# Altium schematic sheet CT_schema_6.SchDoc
size 277 x 170 mm
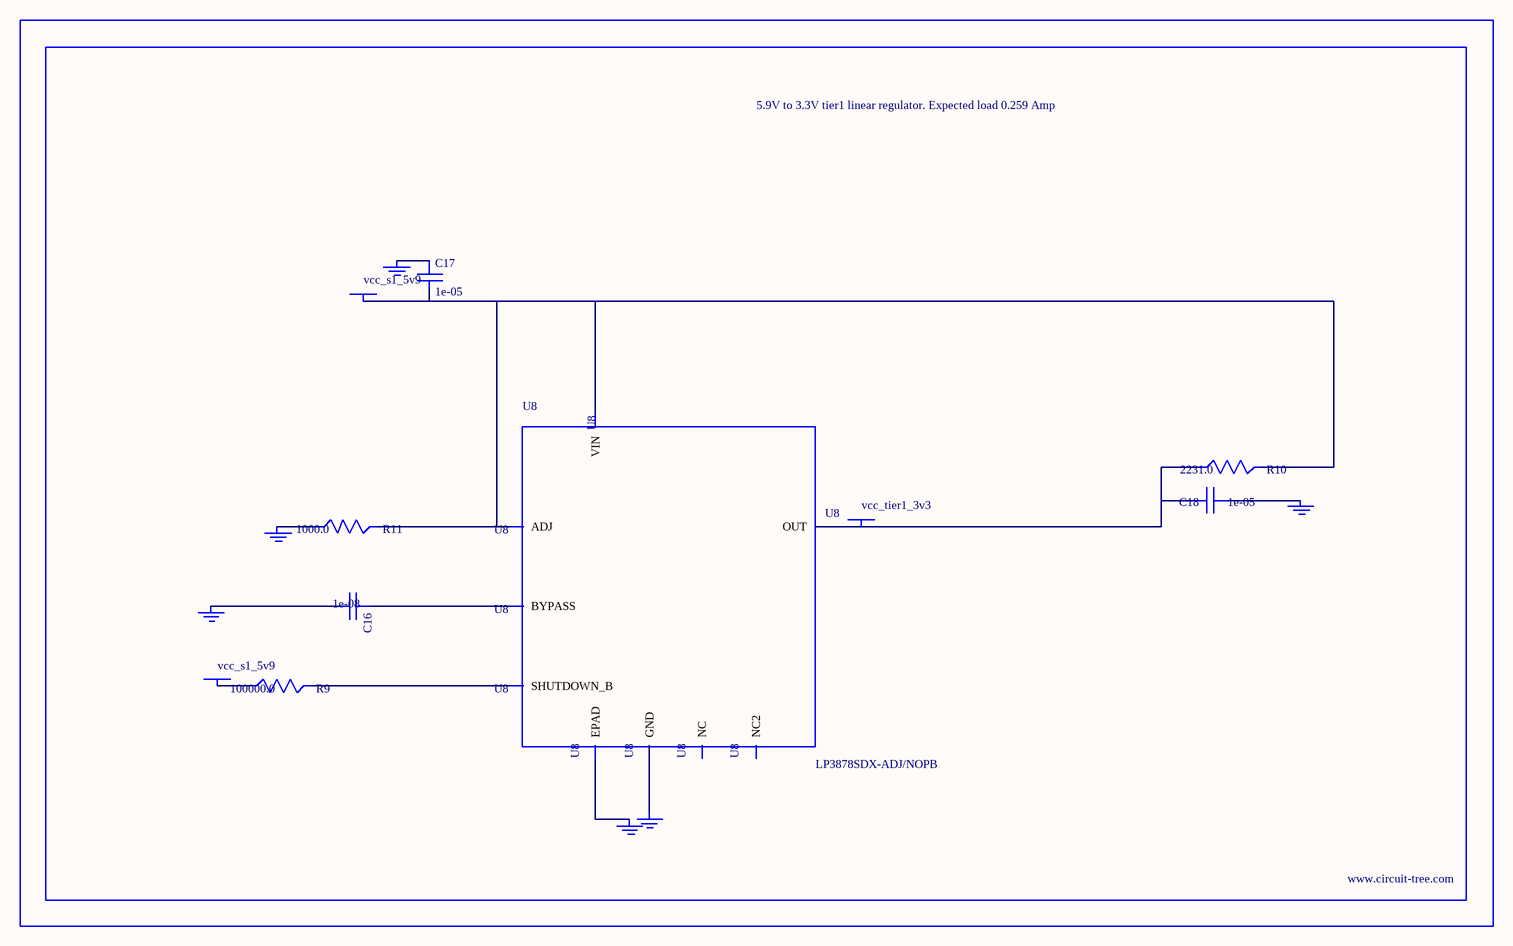
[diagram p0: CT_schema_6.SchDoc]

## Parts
BORDER5  (no value)
C16  1e-08  [C0402]
C17  1e-05  [C1206]
C18  1e-05  [C1210]
GND_INSTANCE_5_0  (no value)
GND_INSTANCE_5_1  (no value)
GND_INSTANCE_5_2  (no value)
GND_INSTANCE_5_3  (no value)
GND_INSTANCE_5_4  (no value)
GND_INSTANCE_5_5  (no value)
POWER_INSTANCE_5_0  vcc_s1_5v9
POWER_INSTANCE_5_1  vcc_s1_5v9
POWER_INSTANCE_5_2  vcc_tier1_3v3
R9  100000.0  [R0603]
R10  2231.0  [R0603]
R11  1000.0  [R0603]
U8  LP3878SDX-ADJ/NOPB  [WSON-8]

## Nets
NetC16_1: C16.1 U8.1(BYPASS)
NetC16_2: C16.2 GND_INSTANCE_5_0.0(GND)
NetC17_1: C17.1 GND_INSTANCE_5_1.0(GND)
NetC17_2: C17.2 POWER_INSTANCE_5_0.0(PWR) R10.2 R11.2 U8.4(VIN) U8.6(ADJ)
NetC18_1: C18.1 GND_INSTANCE_5_2.0(GND)
NetC18_2: C18.2 POWER_INSTANCE_5_2.0(PWR) R10.1 U8.5(OUT)
NetGND_INSTANCE_5_3_0: GND_INSTANCE_5_3.0(GND) R11.1
NetGND_INSTANCE_5_4_0: GND_INSTANCE_5_4.0(GND) U8.PAD(EPAD)
NetGND_INSTANCE_5_5_0: GND_INSTANCE_5_5.0(GND) U8.3(GND)
NetPOWER_INSTANCE_5_1_0: POWER_INSTANCE_5_1.0(PWR) R9.1
NetR9_2: R9.2 U8.8(SHUTDOWN_B)

Not connected (* = marked no-connect by the designer): U8 2(NC) 7(NC2)

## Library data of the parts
BORDER5 = BORDER_PAGE5
C16 = C0402C103K3RAC
C17 = C1206C106K3RACTU
C18 = GRM32DR61E106MA12L
GND_INSTANCE_5_0-GND_INSTANCE_5_5 = GND
POWER_INSTANCE_5_0-POWER_INSTANCE_5_2 = PWR
R9 = RC0603JR-07100KL
R10 = R10
R11 = RC0603JR-071KL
